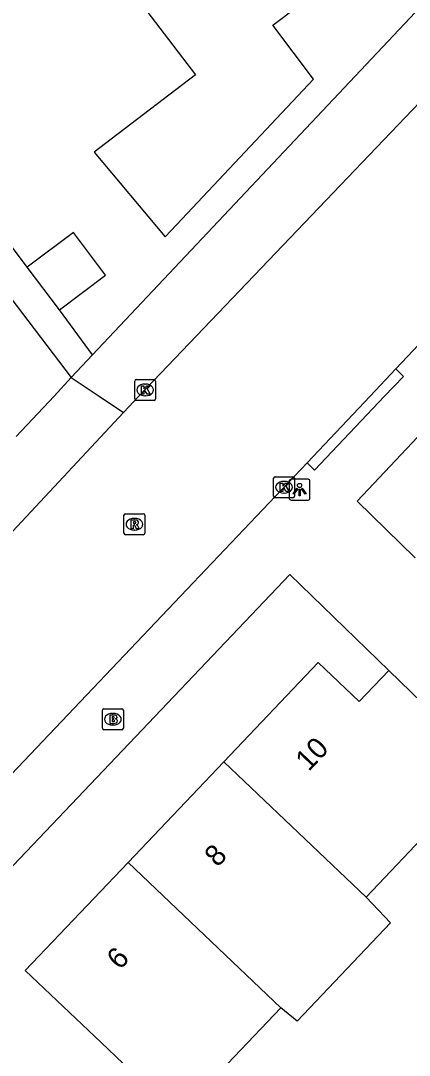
# Model space of a CAD drawing. Extents: x 160037 to 160839, y 385326 to 386441.
# Drawn here: x 160615.01 to 160633.59, y 385468.49 to 385517.96 of the extents above; entities that cross this region are included whole.
import ezdxf

# ---------------------------------------------------------------- set-up
doc = ezdxf.new("R2010")
doc.units = 0
for name, color, linetype in [('IMGEO_Brandkraan', 7, 'Continuous'), ('IMGEO_Kolk', 7, 'Continuous'), ('IMGEO_Lichtpunt', 7, 'Continuous'), ('IMGEO_Pand', 7, 'Continuous'), ('IMGEO_Pand_nummerreeks', 7, 'Continuous'), ('IMGEO_Rijbaan_lokaal_gesloten', 7, 'Continuous'), ('IMGEO_Rijbaan_lokaal_open', 7, 'Continuous'), ('IMGEO_Rioolput', 7, 'Continuous'), ('IMGEO_Voetpad_open', 7, 'Continuous')]:
    doc.layers.add(name, color=color, linetype=linetype)

msp = doc.modelspace()

# ---------------------------------------------------------------- linework, layer by layer
at = {"layer": 'IMGEO_Brandkraan'}
for p, q in [((160618.917, 385484.132), (160618.917, 385484.984)), ((160618.992, 385485.058), (160619.844, 385485.058)), ((160619.405, 385484.838), (160619.43, 385484.838)), ((160619.918, 385484.984), (160619.918, 385484.132)), ((160619.844, 385484.058), (160618.992, 385484.058)), ((160619.428, 385484.278), (160619.403, 385484.278))]:
    msp.add_line(p, q, dxfattribs=at)
for points in [[(160618.917, 385484.132), (160618.917, 385484.984)], [(160618.992, 385485.058), (160619.844, 385485.058)], [(160619.918, 385484.984), (160619.918, 385484.132)], [(160619.265, 385484.758), (160619.265, 385484.358), (160619.478, 385484.358)], [(160619.496, 385484.758), (160619.265, 385484.758)], [(160619.444, 385484.677), (160619.39, 385484.677), (160619.39, 385484.601)], [(160619.39, 385484.601), (160619.443, 385484.601)], [(160619.452, 385484.525), (160619.39, 385484.525), (160619.39, 385484.444)], [(160619.39, 385484.444), (160619.452, 385484.444)], [(160619.844, 385484.058), (160618.992, 385484.058)]]:
    msp.add_lwpolyline(points, dxfattribs=at)
for centre, radius, start, end in [((160618.994, 385484.982), 0.0765, 91.552, 178.448), ((160618.994, 385484.982), 0.0765, 91.552, 178.448), ((160619.842, 385484.982), 0.0765, 1.552, 88.448), ((160619.842, 385484.982), 0.0765, 1.552, 88.448), ((160619.445, 385484.639), 0.0379, 267.8285, 90.9355), ((160619.453, 385484.484), 0.0404, 269.8759, 90.5077), ((160619.484, 385484.609), 0.251, 268.6676, 293.5347), ((160619.5, 385484.613), 0.145, 59.4692, 91.5367), ((160619.525, 385484.66), 0.0922, 285.5137, 58.1501), ((160619.53, 385484.468), 0.105, 301.3115, 78.989), ((160618.994, 385484.134), 0.0765, 181.552, 268.448), ((160618.994, 385484.134), 0.0765, 181.552, 268.448), ((160619.842, 385484.134), 0.0765, 271.552, 358.448), ((160619.842, 385484.134), 0.0765, 271.552, 358.448)]:
    msp.add_arc(centre, radius, start, end, dxfattribs=at)
for centre, major_axis, ratio, start_param, end_param in [((160619.404, 385484.558), (-0.387, 0.002), 0.722429, 4.712389, 7.853982), ((160619.429, 385484.558), (-0.39, 0.002), 0.717154, 1.570796, 4.712389)]:
    msp.add_ellipse(centre, major_axis=major_axis, ratio=ratio, start_param=start_param, end_param=end_param, dxfattribs=at)
at = {"layer": 'IMGEO_Kolk'}
for p, q in [((160620.459, 385499.876), (160620.459, 385500.728)), ((160620.534, 385500.802), (160621.386, 385500.802)), ((160621.46, 385500.728), (160621.46, 385499.876)), ((160620.947, 385500.582), (160620.972, 385500.582)), ((160621.386, 385499.802), (160620.534, 385499.802)), ((160620.97, 385500.022), (160620.945, 385500.022)), ((160627.098, 385495.225), (160627.098, 385496.077)), ((160627.173, 385496.151), (160628.025, 385496.151)), ((160627.586, 385495.931), (160627.611, 385495.931)), ((160628.099, 385496.077), (160628.099, 385495.225)), ((160627.609, 385495.371), (160627.584, 385495.371)), ((160628.025, 385495.151), (160627.173, 385495.151))]:
    msp.add_line(p, q, dxfattribs=at)
for points in [[(160620.459, 385499.876), (160620.459, 385500.728)], [(160620.534, 385500.802), (160621.386, 385500.802)], [(160621.46, 385500.728), (160621.46, 385499.876)], [(160620.78, 385500.502), (160620.903, 385500.502), (160620.903, 385500.351), (160621.033, 385500.502), (160621.197, 385500.502), (160621.051, 385500.351), (160621.204, 385500.102), (160621.052, 385500.102), (160620.967, 385500.266), (160620.903, 385500.199), (160620.903, 385500.102), (160620.78, 385500.102), (160620.78, 385500.502)], [(160621.386, 385499.802), (160620.534, 385499.802)], [(160627.098, 385495.225), (160627.098, 385496.077)], [(160627.173, 385496.151), (160628.025, 385496.151)], [(160627.419, 385495.851), (160627.542, 385495.851), (160627.542, 385495.7), (160627.672, 385495.851), (160627.836, 385495.851), (160627.69, 385495.7), (160627.843, 385495.451), (160627.691, 385495.451), (160627.606, 385495.615), (160627.542, 385495.548), (160627.542, 385495.451), (160627.419, 385495.451), (160627.419, 385495.851)], [(160628.099, 385496.077), (160628.099, 385495.225)], [(160628.025, 385495.151), (160627.173, 385495.151)]]:
    msp.add_lwpolyline(points, dxfattribs=at)
for centre, start, end in [((160620.536, 385500.726), 91.552, 178.448), ((160620.536, 385500.726), 91.552, 178.448), ((160621.384, 385500.726), 1.552, 88.448), ((160621.384, 385500.726), 1.552, 88.448), ((160620.536, 385499.878), 181.552, 268.448), ((160620.536, 385499.878), 181.552, 268.448), ((160621.384, 385499.878), 271.552, 358.448), ((160621.384, 385499.878), 271.552, 358.448), ((160627.175, 385496.075), 91.552, 178.448), ((160627.175, 385496.075), 91.552, 178.448), ((160628.023, 385496.075), 1.552, 88.448), ((160628.023, 385496.075), 1.552, 88.448), ((160627.175, 385495.227), 181.552, 268.448), ((160627.175, 385495.227), 181.552, 268.448), ((160628.023, 385495.227), 271.552, 358.448), ((160628.023, 385495.227), 271.552, 358.448)]:
    msp.add_arc(centre, 0.0765, start, end, dxfattribs=at)
for centre, major_axis, ratio, start_param, end_param in [((160620.946, 385500.302), (-0.387, 0.002), 0.722429, 4.712389, 7.853982), ((160620.971, 385500.302), (-0.39, 0.002), 0.717154, 1.570796, 4.712389), ((160627.585, 385495.651), (-0.387, 0.002), 0.722429, 4.712389, 7.853982), ((160627.61, 385495.651), (-0.39, 0.002), 0.717154, 1.570796, 4.712389)]:
    msp.add_ellipse(centre, major_axis=major_axis, ratio=ratio, start_param=start_param, end_param=end_param, dxfattribs=at)
at = {"layer": 'IMGEO_Lichtpunt'}
for p, q in [((160627.843, 385495.939), (160627.843, 385495.132)), ((160627.843, 385495.939), (160627.843, 385495.132)), ((160628.745, 385496.034), (160627.937, 385496.034)), ((160628.745, 385496.034), (160627.937, 385496.034)), ((160628.839, 385495.132), (160628.839, 385495.939)), ((160628.839, 385495.132), (160628.839, 385495.939)), ((160627.937, 385495.038), (160628.745, 385495.038)), ((160627.937, 385495.038), (160628.745, 385495.038))]:
    msp.add_line(p, q, dxfattribs=at)
for points in [[(160628.217, 385495.603), (160628.256, 385495.575), (160628.068, 385495.313), (160628.03, 385495.34), (160628.217, 385495.603)], [(160628.319, 385495.555), (160628.366, 385495.555), (160628.366, 385495.233), (160628.319, 385495.233), (160628.319, 385495.555)], [(160628.429, 385495.575), (160628.467, 385495.602), (160628.654, 385495.34), (160628.615, 385495.312), (160628.429, 385495.575)]]:
    msp.add_lwpolyline(points, dxfattribs=at)
msp.add_circle((160628.342, 385495.737), 0.0994, dxfattribs=at)
for centre, start, end in [((160627.937, 385495.939), 90, 180), ((160627.937, 385495.939), 90, 180), ((160628.745, 385495.939), 0, 90), ((160628.745, 385495.939), 0, 90), ((160627.937, 385495.132), 180, 270), ((160627.937, 385495.132), 180, 270), ((160628.745, 385495.132), 270, 0), ((160628.745, 385495.132), 270, 360)]:
    msp.add_arc(centre, 0.0946, start, end, dxfattribs=at)
at = {"layer": 'IMGEO_Pand'}
for points in [[(160619.757, 385520.113), (160623.367, 385515.362), (160619.338, 385512.3), (160618.527, 385511.665), (160621.924, 385507.615), (160622.463, 385508.189), (160629.015, 385515.166), (160627.058, 385517.74), (160629.447, 385519.555), (160625.631, 385524.577)], [(160616.861, 385504.13), (160619.067, 385505.795), (160617.53, 385507.831), (160615.324, 385506.167)], [(160616.861, 385504.13), (160615.324, 385506.167)], [(160624.72, 385482.523), (160629.235, 385487.27), (160631.193, 385485.408), (160632.604, 385486.891)], [(160632.604, 385486.891), (160641.563, 385478.207)], [(160620.142, 385477.709), (160624.72, 385482.523)], [(160624.72, 385482.523), (160631.518, 385476.058)], [(160638.961, 385475.47), (160634.759, 385479.466), (160631.518, 385476.058)], [(160627.448, 385470.759), (160624.9, 385468.079), (160626.805, 385466.267), (160624.439, 385463.78), (160618.85, 385469.095), (160615.227, 385472.541), (160620.142, 385477.709)], [(160627.448, 385470.759), (160620.142, 385477.709)], [(160631.518, 385476.058), (160632.691, 385474.816), (160628.222, 385470.117), (160627.448, 385470.759)]]:
    msp.add_lwpolyline(points, dxfattribs=at)
at = {"layer": 'IMGEO_Rijbaan_lokaal_gesloten'}
for points in [[(160619.931, 385499.217), (160620.664, 385500), (160636.496, 385516.585), (160636.604, 385516.708), (160636.727, 385516.848), (160636.886, 385517.029)], [(160642.771, 385511.714), (160632.949, 385501.304)], [(160632.949, 385501.304), (160631.72, 385500), (160628.702, 385496.816)], [(160614.612, 385493.536), (160619.931, 385499.217)], [(160628.702, 385496.816), (160623.258, 385491.075), (160610.371, 385477.516)]]:
    msp.add_lwpolyline(points, dxfattribs=at)
at = {"layer": 'IMGEO_Rijbaan_lokaal_open'}
for points in [[(160598.052, 385526.385), (160617.43, 385500.901)], [(160614.794, 385498.083), (160616.603, 385500), (160617.43, 385500.901)]]:
    msp.add_lwpolyline(points, dxfattribs=at)
at = {"layer": 'IMGEO_Rioolput'}
for p, q in [((160619.945, 385493.456), (160619.945, 385494.308)), ((160620.02, 385494.382), (160620.872, 385494.382)), ((160620.946, 385494.308), (160620.946, 385493.456)), ((160620.433, 385494.162), (160620.458, 385494.162)), ((160620.872, 385493.382), (160620.02, 385493.382)), ((160620.456, 385493.602), (160620.431, 385493.602))]:
    msp.add_line(p, q, dxfattribs=at)
for points in [[(160619.945, 385493.456), (160619.945, 385494.308)], [(160620.02, 385494.382), (160620.872, 385494.382)], [(160620.946, 385494.308), (160620.946, 385493.456)], [(160620.534, 385494.08), (160620.282, 385494.082), (160620.282, 385493.682)], [(160620.282, 385493.682), (160620.406, 385493.682), (160620.406, 385493.844), (160620.417, 385493.844)], [(160620.46, 385494.001), (160620.406, 385494.001), (160620.406, 385493.92)], [(160620.406, 385493.92), (160620.458, 385493.92)], [(160620.464, 385493.815), (160620.535, 385493.682), (160620.675, 385493.682), (160620.61, 385493.808)], [(160620.872, 385493.382), (160620.02, 385493.382)]]:
    msp.add_lwpolyline(points, dxfattribs=at)
for centre, radius, start, end in [((160620.022, 385494.306), 0.0765, 91.552, 178.448), ((160620.022, 385494.306), 0.0765, 91.552, 178.448), ((160620.87, 385494.306), 0.0765, 1.552, 88.448), ((160620.87, 385494.306), 0.0765, 1.552, 88.448), ((160620.416, 385493.791), 0.0533, 26.0293, 88.6989), ((160620.442, 385494.109), 0.19, 274.7715, 282.9687), ((160620.466, 385493.905), 0.0964, 77.0061, 93.1865), ((160620.48, 385493.962), 0.0378, 276.6634, 79.6772), ((160620.533, 385493.97), 0.109, 350.3612, 89.416), ((160620.531, 385493.97), 0.112, 277.5842, 350.9817), ((160620.515, 385493.755), 0.108, 29.5134, 73.7905), ((160620.022, 385493.458), 0.0765, 181.552, 268.448), ((160620.022, 385493.458), 0.0765, 181.552, 268.448), ((160620.87, 385493.458), 0.0765, 271.552, 358.448), ((160620.87, 385493.458), 0.0765, 271.552, 358.448)]:
    msp.add_arc(centre, radius, start, end, dxfattribs=at)
for centre, major_axis, ratio, start_param, end_param in [((160620.432, 385493.882), (-0.387, 0.002), 0.722429, 4.712389, 7.853982), ((160620.457, 385493.882), (-0.39, 0.002), 0.717154, 1.570796, 4.712389)]:
    msp.add_ellipse(centre, major_axis=major_axis, ratio=ratio, start_param=start_param, end_param=end_param, dxfattribs=at)
at = {"layer": 'IMGEO_Voetpad_open'}
for points in [[(160634.139, 385518.639), (160618.449, 385501.983)], [(160708.392, 385506.183), (160651.228, 385512.167), (160645.998, 385510.74), (160635.829, 385500), (160631.087, 385494.991), (160633.869, 385492.281)], [(160615.324, 385506.167), (160612.609, 385509.782)], [(160618.449, 385501.983), (160616.861, 385504.13)], [(160617.43, 385500.901), (160618.449, 385501.983)], [(160632.949, 385501.304), (160633.305, 385500.952), (160632.404, 385500), (160629.063, 385496.471), (160628.702, 385496.816)], [(160617.43, 385500.901), (160618.768, 385500), (160619.931, 385499.217)], [(160632.604, 385486.891), (160627.873, 385491.477), (160597.731, 385459.782)]]:
    msp.add_lwpolyline(points, dxfattribs=at)

# ---------------------------------------------------------------- texts
at = {"layer": 'IMGEO_Pand_nummerreeks'}
for s, p in [('10', (160628.773, 385482.025)), ('8', (160624.42, 385477.449)), ('6', (160619.749, 385472.536))]:
    msp.add_text(s, height=1, rotation=46.4372, dxfattribs=at).set_placement(p)

doc.saveas('drawing.dxf')
